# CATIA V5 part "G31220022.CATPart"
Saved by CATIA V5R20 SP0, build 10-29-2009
Part number: G31220022
Revision: 8
Definition: design
Nomenclature: G31220022
Source: made
Description: NOT SPECIFIED
Bounding box of the stored display mesh (mm): x -8 to 22, y -15.5 to 15.5, z -15.5 to 15.5
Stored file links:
  C:\Users\Raffaele\Desktop\3D X SITO CF\BOLEX\23-BUSH REF 312\G31220022.CATPart

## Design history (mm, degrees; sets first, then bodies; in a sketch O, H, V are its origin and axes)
Body1 "MANIFOLD_SOLID_BREP #5929" (main body)
  Solid1: solid without history
Body2 "MANIFOLD_SOLID_BREP #6072"
  Solid2: solid without history
Body3 "MANIFOLD_SOLID_BREP #6215"
  Solid3: solid without history
Body4 "MANIFOLD_SOLID_BREP #6358"
  Solid4: solid without history
Body5 "MANIFOLD_SOLID_BREP #6501"
  Solid5: solid without history
Body6 "MANIFOLD_SOLID_BREP #6646"
  Solid6: solid without history
Body7 "MANIFOLD_SOLID_BREP #6791"
  Solid7: solid without history
Body8 "MANIFOLD_SOLID_BREP #6936"
  Solid8: solid without history
Body9 "MANIFOLD_SOLID_BREP #7081"
  Solid9: solid without history
Body10 "MANIFOLD_SOLID_BREP #7226"
  Solid10: solid without history
Body11 "MANIFOLD_SOLID_BREP #7371"
  Solid11: solid without history
Body12 "MANIFOLD_SOLID_BREP #7516"
  Solid12: solid without history
Body13 "MANIFOLD_SOLID_BREP #7661"
  Solid13: solid without history
Body14 "MANIFOLD_SOLID_BREP #7806"
  Solid14: solid without history
Body15 "MANIFOLD_SOLID_BREP #7951"
  Solid15: solid without history
Body16 "MANIFOLD_SOLID_BREP #8096"
  Solid16: solid without history
Body17 "MANIFOLD_SOLID_BREP #8241"
  Solid17: solid without history
Body18 "MANIFOLD_SOLID_BREP #8386"
  Solid18: solid without history
Body19 "MANIFOLD_SOLID_BREP #8531"
  Solid19: solid without history
Body20 "MANIFOLD_SOLID_BREP #8676"
  Solid20: solid without history
Body21 "MANIFOLD_SOLID_BREP #8821"
  Solid21: solid without history
Body22 "MANIFOLD_SOLID_BREP #8968"
  Solid22: solid without history
Body23 "MANIFOLD_SOLID_BREP #9113"
  Solid23: solid without history
Body24 "MANIFOLD_SOLID_BREP #9258"
  Solid24: solid without history
Body25 "MANIFOLD_SOLID_BREP #9405"
  Solid25: solid without history
Body26 "MANIFOLD_SOLID_BREP #9550"
  Solid26: solid without history
Body27 "MANIFOLD_SOLID_BREP #9695"
  Solid27: solid without history
Body28 "MANIFOLD_SOLID_BREP #9840"
  Solid28: solid without history
Body29 "MANIFOLD_SOLID_BREP #9985"
  Solid29: solid without history
Body30 "MANIFOLD_SOLID_BREP #10130"
  Solid30: solid without history
Body31 "MANIFOLD_SOLID_BREP #10275"
  Solid31: solid without history
Body32 "MANIFOLD_SOLID_BREP #10418"
  Solid32: solid without history
Body33 "MANIFOLD_SOLID_BREP #10561"
  Solid33: solid without history
Body34 "MANIFOLD_SOLID_BREP #10706"
  Solid34: solid without history
Body35 "MANIFOLD_SOLID_BREP #10851"
  Solid35: solid without history
Body36 "MANIFOLD_SOLID_BREP #10996"
  Solid36: solid without history
Body37 "MANIFOLD_SOLID_BREP #11141"
  Solid37: solid without history
Body38 "MANIFOLD_SOLID_BREP #11288"
  Solid38: solid without history
Body39 "MANIFOLD_SOLID_BREP #11433"
  Solid39: solid without history
Body40 "MANIFOLD_SOLID_BREP #11578"
  Solid40: solid without history
Body41 "MANIFOLD_SOLID_BREP #11725"
  Solid41: solid without history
